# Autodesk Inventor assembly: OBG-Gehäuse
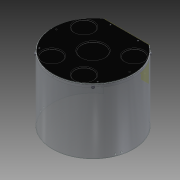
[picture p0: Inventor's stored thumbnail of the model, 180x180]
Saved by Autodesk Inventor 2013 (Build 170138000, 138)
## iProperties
Created: 2012-10
Part Number: OBG-Gehäuse
Document SubType Name: Assembly
Designer: rYan
Author: rYan
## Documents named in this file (8)
- D:\SVN\2013\Inventor\Gehäuse\OBG-Gehäuse.iam
- D:\SVN\2013\Inventor\Gehäuse\MG-Deckel.iam
- MG-Deckel.iam
- D:\SVN\2013\Inventor\Gehäuse\Verbindungsring Deckel.ipt
- D:\SVN\2013\Inventor\Gehäuse\Mantel.ipt
- D:\SVN\2013\Inventor\Gehäuse\Blech vorne.ipt
- D:\SVN\2013\Inventor\Inhaltscenter\de-DE\DIN 7984\DIN 7984 - M3 x 6.ipt
- D:\SVN\2013\Inventor\Inhaltscenter\en-US\DIN 7984\DIN 7984 - M3 x 6.ipt
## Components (14 placed, 5 different names)
1. Verbindungsring Deckel:1 — Passend:4, Passend:5, Passend:6, Passend:7, Passend:8, Passend:9, Passend:19, Passend:20, Passend:21, Passend:23, Passend:25, Passend:27, Passend:29, Passend:30, Passend:31
2. MG-Deckel:1 [sub-assembly] — Passend:6, Passend:30, Passend:31
3. Mantel:1 — Passend:4, Passend:5
4. Blech vorne:1 — Passend:7, Passend:8, Passend:9, Mate:33, Mate:35
5. DIN 7984 M3 x 6:1
6. DIN 7984 M3 x 6:2 — Passend:20
7. DIN 7984 M3 x 6:3 — Passend:21
8. DIN 7984 M3 x 6:4 — Passend:19
9. DIN 7984 M3 x 6:5 — Passend:23
10. DIN 7984 M3 x 6:6 — Passend:25
11. DIN 7984 M3 x 6:7 — Passend:27
12. DIN 7984 M3 x 6:8 — Passend:29
13. DIN 7984 M3 x 6:9 — Mate:33
14. DIN 7984 M3 x 6:10 — Mate:35
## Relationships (17: Mate 17)
- Passend:4 [Mate]: Verbindungsring Deckel:1 ↔ Mantel:1
- Passend:5 [Mate]: Verbindungsring Deckel:1 ↔ Mantel:1
- Passend:6 [Mate]: Verbindungsring Deckel:1 ↔ MG-Deckel:1
- Passend:7 [Mate]: Verbindungsring Deckel:1 ↔ Blech vorne:1
- Passend:8 [Mate]: Verbindungsring Deckel:1 ↔ Blech vorne:1
- Passend:9 [Mate]: Verbindungsring Deckel:1 ↔ Blech vorne:1
- Passend:19 [Mate]: Verbindungsring Deckel:1 ↔ DIN 7984 M3 x 6:4
- Passend:20 [Mate]: Verbindungsring Deckel:1 ↔ DIN 7984 M3 x 6:2
- Passend:21 [Mate]: Verbindungsring Deckel:1 ↔ DIN 7984 M3 x 6:3
- Passend:23 [Mate]: Verbindungsring Deckel:1 ↔ DIN 7984 M3 x 6:5
- Passend:25 [Mate]: Verbindungsring Deckel:1 ↔ DIN 7984 M3 x 6:6
- Passend:27 [Mate]: Verbindungsring Deckel:1 ↔ DIN 7984 M3 x 6:7
- Passend:29 [Mate]: Verbindungsring Deckel:1 ↔ DIN 7984 M3 x 6:8
- Passend:30 [Mate]: Verbindungsring Deckel:1 ↔ MG-Deckel:1
- Passend:31 [Mate]: Verbindungsring Deckel:1 ↔ MG-Deckel:1
- Mate:33: Blech vorne:1 ↔ DIN 7984 M3 x 6:9
- Mate:35: Blech vorne:1 ↔ DIN 7984 M3 x 6:10
